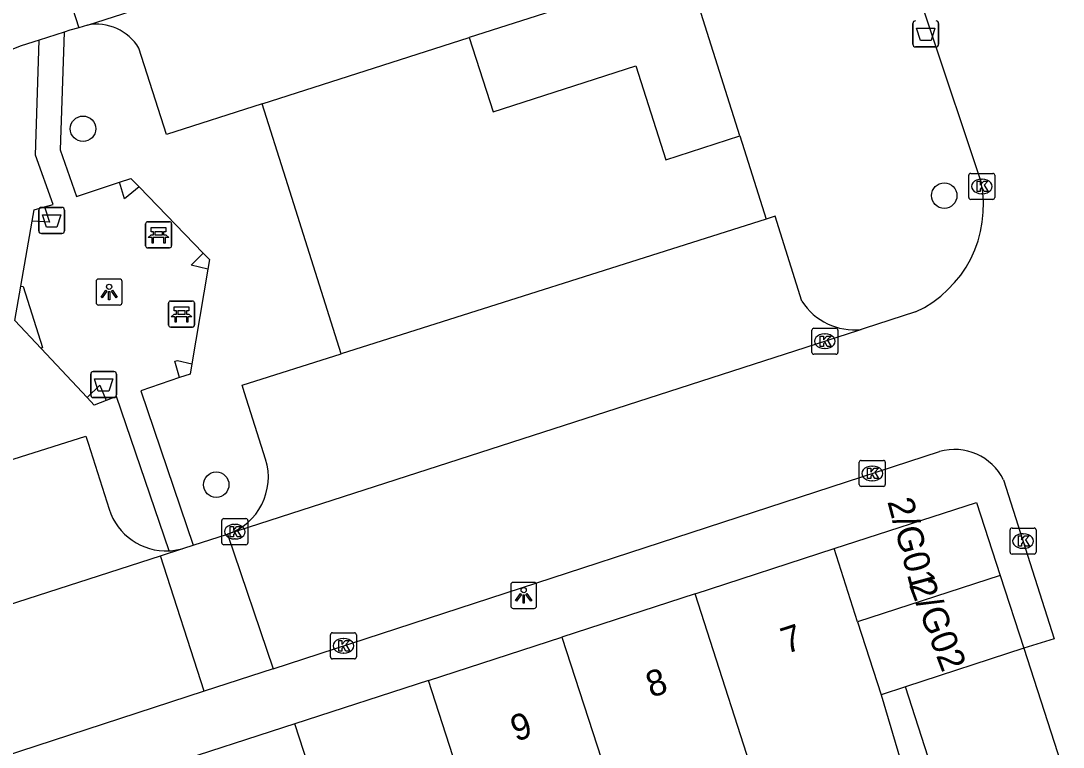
# Model space of a CAD drawing. Extents: x 159377 to 159983, y 382996 to 383595.
# Drawn here: x 159543.65 to 159583.72, y 383099.82 to 383127.71 of the extents above; entities that cross this region are included whole.
import ezdxf

# ---------------------------------------------------------------- set-up
doc = ezdxf.new("R2010")
doc.units = 0
for name, color, linetype in [('IMGEO_Afvalbak', 7, 'Continuous'), ('IMGEO_Bank', 7, 'Continuous'), ('IMGEO_Boom', 7, 'Continuous'), ('IMGEO_Groenvoorziening', 7, 'Continuous'), ('IMGEO_Kolk', 7, 'Continuous'), ('IMGEO_Lichtpunt', 7, 'Continuous'), ('IMGEO_Pand', 7, 'Continuous'), ('IMGEO_Pand_nummerreeks', 7, 'Continuous'), ('IMGEO_Parkeervlak_open', 7, 'Continuous'), ('IMGEO_Rijbaan_lokaal_open', 7, 'Continuous'), ('IMGEO_Voetpad_halfverhard', 7, 'Continuous'), ('IMGEO_Voetpad_open', 7, 'Continuous')]:
    doc.layers.add(name, color=color, linetype=linetype)

msp = doc.modelspace()

# ---------------------------------------------------------------- linework, layer by layer
at = {"layer": 'IMGEO_Afvalbak'}
for p, q in [((159577.943, 383126.815), (159577.943, 383127.615)), ((159577.943, 383127.615), (159577.943, 383126.815)), ((159578.933, 383127.615), (159578.933, 383126.815)), ((159578.933, 383126.815), (159578.933, 383127.615)), ((159578.833, 383126.715), (159578.043, 383126.715)), ((159578.043, 383126.715), (159578.833, 383126.715)), ((159544.338, 383119.648), (159544.338, 383120.448)), ((159544.338, 383120.448), (159544.338, 383119.648)), ((159544.438, 383120.548), (159545.228, 383120.548)), ((159545.228, 383120.548), (159544.438, 383120.548)), ((159545.328, 383120.448), (159545.328, 383119.648)), ((159545.328, 383119.648), (159545.328, 383120.448)), ((159545.228, 383119.548), (159544.438, 383119.548)), ((159544.438, 383119.548), (159545.228, 383119.548)), ((159546.336, 383113.344), (159546.336, 383114.144)), ((159546.336, 383114.144), (159546.336, 383113.344)), ((159546.436, 383114.244), (159547.226, 383114.244)), ((159547.226, 383114.244), (159546.436, 383114.244)), ((159547.326, 383114.144), (159547.326, 383113.344)), ((159547.326, 383113.344), (159547.326, 383114.144)), ((159547.226, 383113.244), (159546.436, 383113.244)), ((159546.436, 383113.244), (159547.226, 383113.244))]:
    msp.add_line(p, q, dxfattribs=at)
for points in [[(159578.086, 383127.429), (159578.79, 383127.429), (159578.641, 383126.959), (159578.235, 383126.959), (159578.086, 383127.429)], [(159544.481, 383120.262), (159545.185, 383120.262), (159545.036, 383119.792), (159544.63, 383119.792), (159544.481, 383120.262)], [(159546.479, 383113.958), (159547.183, 383113.958), (159547.034, 383113.488), (159546.628, 383113.488), (159546.479, 383113.958)]]:
    msp.add_lwpolyline(points, dxfattribs=at)
for centre, start, end in [((159578.043, 383127.615), 90, 180), ((159578.043, 383127.615), 90, 180), ((159578.833, 383127.615), 0, 90), ((159578.833, 383127.615), 360, 90), ((159578.043, 383126.815), 180, 270), ((159578.043, 383126.815), 180, 270), ((159578.833, 383126.815), 270, 0), ((159578.833, 383126.815), 270, 0), ((159544.438, 383120.448), 90, 180), ((159544.438, 383120.448), 90, 180), ((159545.228, 383120.448), 0, 90), ((159545.228, 383120.448), 360, 90), ((159544.438, 383119.648), 180, 270), ((159544.438, 383119.648), 180, 270), ((159545.228, 383119.648), 270, 0), ((159545.228, 383119.648), 270, 0), ((159546.436, 383114.144), 90, 180), ((159546.436, 383114.144), 90, 180), ((159547.226, 383114.144), 0, 90), ((159547.226, 383114.144), 360, 90), ((159546.436, 383113.344), 180, 270), ((159546.436, 383113.344), 180, 270), ((159547.226, 383113.344), 270, 0), ((159547.226, 383113.344), 270, 0)]:
    msp.add_arc(centre, 0.1, start, end, dxfattribs=at)
at = {"layer": 'IMGEO_Bank'}
for p, q in [((159548.445, 383119.071), (159548.445, 383119.912)), ((159548.445, 383119.912), (159548.445, 383119.071)), ((159548.52, 383119.996), (159549.361, 383119.996)), ((159549.361, 383119.996), (159548.52, 383119.996)), ((159549.445, 383119.921), (159549.445, 383119.08)), ((159549.445, 383119.08), (159549.445, 383119.921)), ((159549.142, 383119.394), (159548.749, 383119.394)), ((159548.754, 383119.502), (159548.754, 383119.608)), ((159548.798, 383119.608), (159548.798, 383119.502)), ((159549.086, 383119.614), (159548.804, 383119.614)), ((159548.804, 383119.496), (159549.086, 383119.496)), ((159549.092, 383119.502), (159549.092, 383119.608)), ((159549.136, 383119.608), (159549.136, 383119.502)), ((159549.37, 383118.996), (159548.529, 383118.996)), ((159548.529, 383118.996), (159549.37, 383118.996)), ((159549.326, 383116.028), (159549.326, 383116.869)), ((159549.326, 383116.869), (159549.326, 383116.028)), ((159549.401, 383116.953), (159550.242, 383116.953)), ((159550.242, 383116.953), (159549.401, 383116.953)), ((159550.326, 383116.878), (159550.326, 383116.037)), ((159550.326, 383116.037), (159550.326, 383116.878)), ((159549.635, 383116.459), (159549.635, 383116.565)), ((159549.679, 383116.565), (159549.679, 383116.459)), ((159549.967, 383116.571), (159549.685, 383116.571)), ((159549.685, 383116.453), (159549.967, 383116.453)), ((159549.973, 383116.459), (159549.973, 383116.565)), ((159550.017, 383116.565), (159550.017, 383116.459)), ((159550.023, 383116.351), (159549.63, 383116.351)), ((159550.251, 383115.953), (159549.41, 383115.953)), ((159549.41, 383115.953), (159550.251, 383115.953))]:
    msp.add_line(p, q, dxfattribs=at)
for points in [[(159548.748, 383119.614), (159548.662, 383119.614), (159548.662, 383119.775), (159549.225, 383119.775), (159549.225, 383119.614), (159549.142, 383119.614)], [(159548.692, 383119.394), (159548.55, 383119.394), (159548.662, 383119.496), (159548.748, 383119.496)], [(159548.742, 383119.387), (159548.742, 383119.18), (159548.699, 383119.18), (159548.699, 383119.387)], [(159549.142, 383119.496), (159549.225, 383119.496), (159549.337, 383119.394), (159549.198, 383119.394)], [(159549.192, 383119.387), (159549.192, 383119.18), (159549.148, 383119.18), (159549.148, 383119.387)], [(159549.573, 383116.351), (159549.431, 383116.351), (159549.543, 383116.453), (159549.629, 383116.453)], [(159549.629, 383116.571), (159549.543, 383116.571), (159549.543, 383116.732), (159550.106, 383116.732), (159550.106, 383116.571), (159550.023, 383116.571)], [(159550.023, 383116.453), (159550.106, 383116.453), (159550.218, 383116.351), (159550.079, 383116.351)], [(159549.623, 383116.344), (159549.623, 383116.137), (159549.58, 383116.137), (159549.58, 383116.344)], [(159550.073, 383116.344), (159550.073, 383116.137), (159550.029, 383116.137), (159550.029, 383116.344)]]:
    msp.add_lwpolyline(points, dxfattribs=at)
for centre, radius, start, end in [((159548.523, 383119.918), 0.0779, 92.4484, 184.2845), ((159548.523, 383119.918), 0.0779, 92.4484, 184.2845), ((159549.367, 383119.918), 0.0779, 2.4484, 94.2845), ((159549.367, 383119.918), 0.0779, 2.4484, 94.2845), ((159548.692, 383119.387), 0.00671, 2.8957, 87.1043), ((159548.749, 383119.387), 0.00671, 92.8957, 177.1043), ((159548.747, 383119.607), 0.00671, 2.8957, 87.1043), ((159548.747, 383119.503), 0.00671, 272.8957, 357.1043), ((159548.804, 383119.607), 0.00671, 92.8957, 177.1043), ((159548.804, 383119.503), 0.00671, 182.8957, 267.1043), ((159549.086, 383119.607), 0.00671, 2.8957, 87.1043), ((159549.086, 383119.503), 0.00671, 272.8957, 357.1043), ((159549.143, 383119.607), 0.00671, 92.8957, 177.1043), ((159549.143, 383119.503), 0.00671, 182.8957, 267.1043), ((159549.141, 383119.387), 0.00671, 2.8957, 87.1043), ((159549.198, 383119.387), 0.00671, 92.8957, 177.1043), ((159548.523, 383119.074), 0.0779, 182.4484, 274.2845), ((159548.523, 383119.074), 0.0779, 182.4484, 274.2845), ((159549.367, 383119.074), 0.0779, 272.4484, 4.2845), ((159549.367, 383119.074), 0.0779, 272.4484, 4.2845), ((159549.404, 383116.875), 0.0779, 92.4484, 184.2845), ((159549.404, 383116.875), 0.0779, 92.4484, 184.2845), ((159550.248, 383116.875), 0.0779, 2.4484, 94.2845), ((159550.248, 383116.875), 0.0779, 2.4484, 94.2845), ((159549.628, 383116.564), 0.00671, 2.8957, 87.1043), ((159549.628, 383116.46), 0.00671, 272.8957, 357.1043), ((159549.685, 383116.564), 0.00671, 92.8957, 177.1043), ((159549.685, 383116.46), 0.00671, 182.8957, 267.1043), ((159549.967, 383116.564), 0.00671, 2.8957, 87.1043), ((159549.967, 383116.46), 0.00671, 272.8957, 357.1043), ((159550.024, 383116.564), 0.00671, 92.8957, 177.1043), ((159550.024, 383116.46), 0.00671, 182.8957, 267.1043), ((159549.404, 383116.031), 0.0779, 182.4484, 274.2845), ((159549.404, 383116.031), 0.0779, 182.4484, 274.2845), ((159549.573, 383116.344), 0.00671, 2.8957, 87.1043), ((159549.63, 383116.344), 0.00671, 92.8957, 177.1043), ((159550.022, 383116.344), 0.00671, 2.8957, 87.1043), ((159550.079, 383116.344), 0.00671, 92.8957, 177.1043), ((159550.248, 383116.031), 0.0779, 272.4484, 4.2845), ((159550.248, 383116.031), 0.0779, 272.4484, 4.2845)]:
    msp.add_arc(centre, radius, start, end, dxfattribs=at)
at = {"layer": 'IMGEO_Boom'}
for centre in [(159546.04, 383123.57), (159579.15, 383121.002), (159551.161, 383109.897)]:
    msp.add_circle(centre, 0.489, dxfattribs=at)
at = {"layer": 'IMGEO_Groenvoorziening'}
for points in [[(159571.294, 383123.299), (159569.251, 383129.752)], [(159560.89, 383127.076), (159561.803, 383124.221), (159567.297, 383125.984), (159568.44, 383122.376), (159571.294, 383123.299)], [(159555.969, 383114.93), (159553.836, 383121.665), (159552.93, 383124.528)], [(159571.294, 383123.299), (159571.459, 383122.778), (159572.307, 383120.099)], [(159547.442, 383121.513), (159547.884, 383121.66), (159548.198, 383121.336)], [(159544.083, 383120.022), (159544.158, 383120.452), (159544.563, 383120.57)], [(159550.658, 383118.797), (159550.906, 383118.542), (159550.844, 383118.175)], [(159544.43, 383115.124), (159543.419, 383116.198), (159543.65, 383117.526)], [(159550.226, 383114.542), (159550.158, 383114.146), (159549.753, 383114.009)], [(159546.924, 383113.129), (159546.472, 383112.957), (159546.197, 383113.249)]]:
    msp.add_lwpolyline(points, dxfattribs=at)
at = {"layer": 'IMGEO_Kolk'}
for p, q in [((159580.093, 383120.93), (159580.093, 383121.782)), ((159580.168, 383121.856), (159581.02, 383121.856)), ((159581.094, 383121.782), (159581.094, 383120.93)), ((159580.581, 383121.636), (159580.606, 383121.636)), ((159581.02, 383120.856), (159580.168, 383120.856)), ((159580.604, 383121.076), (159580.579, 383121.076)), ((159574.059, 383114.981), (159574.059, 383115.833)), ((159574.134, 383115.907), (159574.986, 383115.907)), ((159574.547, 383115.687), (159574.572, 383115.687)), ((159575.06, 383115.833), (159575.06, 383114.981)), ((159574.986, 383114.907), (159574.134, 383114.907)), ((159574.57, 383115.127), (159574.545, 383115.127)), ((159575.958, 383110.83), (159576.81, 383110.83)), ((159575.883, 383109.904), (159575.883, 383110.756)), ((159576.371, 383110.61), (159576.396, 383110.61)), ((159576.884, 383110.756), (159576.884, 383109.904)), ((159576.394, 383110.05), (159576.369, 383110.05)), ((159576.81, 383109.83), (159575.958, 383109.83)), ((159551.376, 383107.666), (159551.376, 383108.518)), ((159551.451, 383108.592), (159552.303, 383108.592)), ((159552.377, 383108.518), (159552.377, 383107.666)), ((159551.864, 383108.372), (159551.889, 383108.372)), ((159581.68, 383107.307), (159581.68, 383108.159)), ((159581.755, 383108.233), (159582.607, 383108.233)), ((159582.168, 383108.013), (159582.193, 383108.013)), ((159582.681, 383108.159), (159582.681, 383107.307)), ((159551.887, 383107.812), (159551.862, 383107.812)), ((159552.303, 383107.592), (159551.451, 383107.592)), ((159582.607, 383107.233), (159581.755, 383107.233)), ((159582.191, 383107.453), (159582.166, 383107.453)), ((159555.552, 383103.28), (159555.552, 383104.132)), ((159555.627, 383104.206), (159556.479, 383104.206)), ((159556.553, 383104.132), (159556.553, 383103.28)), ((159556.04, 383103.986), (159556.065, 383103.986)), ((159556.479, 383103.206), (159555.627, 383103.206)), ((159556.063, 383103.426), (159556.038, 383103.426))]:
    msp.add_line(p, q, dxfattribs=at)
for points in [[(159580.093, 383120.93), (159580.093, 383121.782)], [(159580.168, 383121.856), (159581.02, 383121.856)], [(159581.094, 383121.782), (159581.094, 383120.93)], [(159580.414, 383121.556), (159580.537, 383121.556), (159580.537, 383121.405), (159580.667, 383121.556), (159580.831, 383121.556), (159580.685, 383121.405), (159580.838, 383121.156), (159580.686, 383121.156), (159580.601, 383121.32), (159580.537, 383121.253), (159580.537, 383121.156), (159580.414, 383121.156), (159580.414, 383121.556)], [(159581.02, 383120.856), (159580.168, 383120.856)], [(159574.059, 383114.981), (159574.059, 383115.833)], [(159574.134, 383115.907), (159574.986, 383115.907)], [(159575.06, 383115.833), (159575.06, 383114.981)], [(159574.38, 383115.607), (159574.503, 383115.607), (159574.503, 383115.456), (159574.633, 383115.607), (159574.797, 383115.607), (159574.651, 383115.456), (159574.804, 383115.207), (159574.652, 383115.207), (159574.567, 383115.371), (159574.503, 383115.304), (159574.503, 383115.207), (159574.38, 383115.207), (159574.38, 383115.607)], [(159574.986, 383114.907), (159574.134, 383114.907)], [(159575.958, 383110.83), (159576.81, 383110.83)], [(159575.883, 383109.904), (159575.883, 383110.756)], [(159576.204, 383110.53), (159576.327, 383110.53), (159576.327, 383110.379), (159576.457, 383110.53), (159576.621, 383110.53), (159576.475, 383110.379), (159576.628, 383110.13), (159576.476, 383110.13), (159576.391, 383110.294), (159576.327, 383110.227), (159576.327, 383110.13), (159576.204, 383110.13), (159576.204, 383110.53)], [(159576.884, 383110.756), (159576.884, 383109.904)], [(159576.81, 383109.83), (159575.958, 383109.83)], [(159551.376, 383107.666), (159551.376, 383108.518)], [(159551.451, 383108.592), (159552.303, 383108.592)], [(159552.377, 383108.518), (159552.377, 383107.666)], [(159551.697, 383108.292), (159551.82, 383108.292), (159551.82, 383108.141), (159551.95, 383108.292), (159552.114, 383108.292), (159551.968, 383108.141), (159552.121, 383107.892), (159551.969, 383107.892), (159551.884, 383108.056), (159551.82, 383107.989), (159551.82, 383107.892), (159551.697, 383107.892), (159551.697, 383108.292)], [(159581.68, 383107.307), (159581.68, 383108.159)], [(159581.755, 383108.233), (159582.607, 383108.233)], [(159582.681, 383108.159), (159582.681, 383107.307)], [(159582.001, 383107.933), (159582.124, 383107.933), (159582.124, 383107.782), (159582.254, 383107.933), (159582.418, 383107.933), (159582.272, 383107.782), (159582.425, 383107.533), (159582.273, 383107.533), (159582.188, 383107.697), (159582.124, 383107.63), (159582.124, 383107.533), (159582.001, 383107.533), (159582.001, 383107.933)], [(159552.303, 383107.592), (159551.451, 383107.592)], [(159582.607, 383107.233), (159581.755, 383107.233)], [(159555.552, 383103.28), (159555.552, 383104.132)], [(159555.627, 383104.206), (159556.479, 383104.206)], [(159556.553, 383104.132), (159556.553, 383103.28)], [(159555.873, 383103.906), (159555.996, 383103.906), (159555.996, 383103.755), (159556.126, 383103.906), (159556.29, 383103.906), (159556.144, 383103.755), (159556.297, 383103.506), (159556.145, 383103.506), (159556.06, 383103.67), (159555.996, 383103.603), (159555.996, 383103.506), (159555.873, 383103.506), (159555.873, 383103.906)], [(159556.479, 383103.206), (159555.627, 383103.206)]]:
    msp.add_lwpolyline(points, dxfattribs=at)
for centre, start, end in [((159580.17, 383121.78), 91.552, 178.448), ((159580.17, 383121.78), 91.552, 178.448), ((159581.018, 383121.78), 1.552, 88.448), ((159581.018, 383121.78), 1.552, 88.448), ((159580.17, 383120.932), 181.552, 268.448), ((159580.17, 383120.932), 181.552, 268.448), ((159581.018, 383120.932), 271.552, 358.448), ((159581.018, 383120.932), 271.552, 358.448), ((159574.136, 383115.831), 91.552, 178.448), ((159574.136, 383115.831), 91.552, 178.448), ((159574.984, 383115.831), 1.552, 88.448), ((159574.984, 383115.831), 1.552, 88.448), ((159574.136, 383114.983), 181.552, 268.448), ((159574.136, 383114.983), 181.552, 268.448), ((159574.984, 383114.983), 271.552, 358.448), ((159574.984, 383114.983), 271.552, 358.448), ((159575.96, 383110.754), 91.552, 178.448), ((159575.96, 383110.754), 91.552, 178.448), ((159576.808, 383110.754), 1.552, 88.448), ((159576.808, 383110.754), 1.552, 88.448), ((159575.96, 383109.906), 181.552, 268.448), ((159575.96, 383109.906), 181.552, 268.448), ((159576.808, 383109.906), 271.552, 358.448), ((159576.808, 383109.906), 271.552, 358.448), ((159551.453, 383108.516), 91.552, 178.448), ((159551.453, 383108.516), 91.552, 178.448), ((159552.301, 383108.516), 1.552, 88.448), ((159552.301, 383108.516), 1.552, 88.448), ((159581.757, 383108.157), 91.552, 178.448), ((159581.757, 383108.157), 91.552, 178.448), ((159582.605, 383108.157), 1.552, 88.448), ((159582.605, 383108.157), 1.552, 88.448), ((159551.453, 383107.668), 181.552, 268.448), ((159551.453, 383107.668), 181.552, 268.448), ((159552.301, 383107.668), 271.552, 358.448), ((159552.301, 383107.668), 271.552, 358.448), ((159581.757, 383107.309), 181.552, 268.448), ((159581.757, 383107.309), 181.552, 268.448), ((159582.605, 383107.309), 271.552, 358.448), ((159582.605, 383107.309), 271.552, 358.448), ((159555.629, 383104.13), 91.552, 178.448), ((159555.629, 383104.13), 91.552, 178.448), ((159556.477, 383104.13), 1.552, 88.448), ((159556.477, 383104.13), 1.552, 88.448), ((159555.629, 383103.282), 181.552, 268.448), ((159555.629, 383103.282), 181.552, 268.448), ((159556.477, 383103.282), 271.552, 358.448), ((159556.477, 383103.282), 271.552, 358.448)]:
    msp.add_arc(centre, 0.0765, start, end, dxfattribs=at)
for centre, major_axis, ratio, start_param, end_param in [((159580.58, 383121.356), (-0.387, 0.002), 0.722429, 4.712389, 7.853982), ((159580.605, 383121.356), (-0.39, 0.002), 0.717154, 1.570796, 4.712389), ((159574.546, 383115.407), (-0.387, 0.002), 0.722429, 4.712389, 7.853982), ((159574.571, 383115.407), (-0.39, 0.002), 0.717154, 1.570796, 4.712389), ((159576.37, 383110.33), (-0.387, 0.002), 0.722429, 4.712389, 7.853982), ((159576.395, 383110.33), (-0.39, 0.002), 0.717154, 1.570796, 4.712389), ((159551.863, 383108.092), (-0.387, 0.002), 0.722429, 4.712389, 7.853982), ((159551.888, 383108.092), (-0.39, 0.002), 0.717154, 1.570796, 4.712389), ((159582.167, 383107.733), (-0.387, 0.002), 0.722429, 4.712389, 7.853982), ((159582.192, 383107.733), (-0.39, 0.002), 0.717154, 1.570796, 4.712389), ((159556.039, 383103.706), (-0.387, 0.002), 0.722429, 4.712389, 7.853982), ((159556.064, 383103.706), (-0.39, 0.002), 0.717154, 1.570796, 4.712389)]:
    msp.add_ellipse(centre, major_axis=major_axis, ratio=ratio, start_param=start_param, end_param=end_param, dxfattribs=at)
at = {"layer": 'IMGEO_Lichtpunt'}
for p, q in [((159546.545, 383117.701), (159546.545, 383116.894)), ((159546.545, 383117.701), (159546.545, 383116.894)), ((159547.447, 383117.796), (159546.639, 383117.796)), ((159547.447, 383117.796), (159546.639, 383117.796)), ((159547.541, 383116.894), (159547.541, 383117.701)), ((159547.541, 383116.894), (159547.541, 383117.701)), ((159546.639, 383116.8), (159547.447, 383116.8)), ((159546.639, 383116.8), (159547.447, 383116.8)), ((159562.483, 383106.048), (159562.483, 383105.241)), ((159562.483, 383106.048), (159562.483, 383105.241)), ((159563.385, 383106.143), (159562.577, 383106.143)), ((159563.385, 383106.143), (159562.577, 383106.143)), ((159563.479, 383105.241), (159563.479, 383106.048)), ((159563.479, 383105.241), (159563.479, 383106.048)), ((159562.577, 383105.147), (159563.385, 383105.147)), ((159562.577, 383105.147), (159563.385, 383105.147))]:
    msp.add_line(p, q, dxfattribs=at)
for points in [[(159546.919, 383117.365), (159546.958, 383117.337), (159546.77, 383117.075), (159546.732, 383117.102), (159546.919, 383117.365)], [(159547.021, 383117.317), (159547.068, 383117.317), (159547.068, 383116.995), (159547.021, 383116.995), (159547.021, 383117.317)], [(159547.131, 383117.337), (159547.169, 383117.364), (159547.356, 383117.102), (159547.317, 383117.074), (159547.131, 383117.337)], [(159562.857, 383105.712), (159562.896, 383105.684), (159562.708, 383105.422), (159562.67, 383105.449), (159562.857, 383105.712)], [(159562.959, 383105.664), (159563.006, 383105.664), (159563.006, 383105.342), (159562.959, 383105.342), (159562.959, 383105.664)], [(159563.069, 383105.684), (159563.107, 383105.711), (159563.294, 383105.449), (159563.255, 383105.421), (159563.069, 383105.684)]]:
    msp.add_lwpolyline(points, dxfattribs=at)
for centre in [(159547.044, 383117.499), (159562.982, 383105.846)]:
    msp.add_circle(centre, 0.0994, dxfattribs=at)
for centre, start, end in [((159546.639, 383117.701), 90, 180), ((159546.639, 383117.701), 90, 180), ((159547.447, 383117.701), 0, 90), ((159547.447, 383117.701), 0, 90), ((159546.639, 383116.894), 180, 270), ((159546.639, 383116.894), 180, 270), ((159547.447, 383116.894), 270, 0), ((159547.447, 383116.894), 270, 360), ((159562.577, 383106.048), 90, 180), ((159562.577, 383106.048), 90, 180), ((159563.385, 383106.048), 0, 90), ((159563.385, 383106.048), 0, 90), ((159562.577, 383105.241), 180, 270), ((159562.577, 383105.241), 180, 270), ((159563.385, 383105.241), 270, 0), ((159563.385, 383105.241), 270, 360)]:
    msp.add_arc(centre, 0.0946, start, end, dxfattribs=at)
at = {"layer": 'IMGEO_Pand'}
for points in [[(159574.918, 383107.441), (159580.39, 383109.217), (159581.3, 383106.414)], [(159569.577, 383105.707), (159574.918, 383107.441)], [(159575.821, 383104.635), (159574.918, 383107.441)], [(159581.3, 383106.414), (159575.821, 383104.635)], [(159581.3, 383106.414), (159582.21, 383103.611)], [(159569.577, 383105.707), (159564.446, 383104.041)], [(159572.256, 383097.384), (159569.577, 383105.707)], [(159575.821, 383104.635), (159576.724, 383101.831)], [(159559.316, 383102.376), (159564.446, 383104.041)], [(159564.446, 383104.041), (159567.152, 383095.728)], [(159582.21, 383103.611), (159577.654, 383102.133)], [(159559.316, 383102.376), (159554.184, 383100.71)], [(159562.01, 383094.058), (159559.316, 383102.376)], [(159577.654, 383102.133), (159576.724, 383101.831)], [(159576.724, 383101.831), (159577.533, 383099.097)], [(159554.184, 383100.71), (159549.045, 383099.042)], [(159556.888, 383092.396), (159554.184, 383100.71)]]:
    msp.add_lwpolyline(points, dxfattribs=at)
at = {"layer": 'IMGEO_Parkeervlak_open'}
for points in [[(159569.251, 383129.752), (159560.89, 383127.076)], [(159552.93, 383124.528), (159560.89, 383127.076)], [(159552.93, 383124.528), (159549.248, 383123.349), (159548.186, 383126.668)], [(159572.307, 383120.099), (159555.969, 383114.93)], [(159573.679, 383116.948), (159572.649, 383120.207), (159572.307, 383120.099)], [(159553.057, 383110.875), (159552.25, 383113.426), (159552.156, 383113.724), (159555.969, 383114.93)], [(159542.373, 383110.568), (159546.154, 383111.766), (159546.242, 383111.488), (159547.042, 383108.961)]]:
    msp.add_lwpolyline(points, dxfattribs=at)
for centre, radius, start, end in [((159546.565, 383125.692), 1.893, 31.055, 100.7673), ((159575.69, 383118.23), 2.385, 212.5102, 276.489), ((159550.862, 383110.182), 2.302, 288.4865, 17.526), ((159549.233, 383109.652), 2.297, 197.4994, 273.0305)]:
    msp.add_arc(centre, radius, start, end, dxfattribs=at)
at = {"layer": 'IMGEO_Rijbaan_lokaal_open'}
for points in [[(159546.211, 383127.551), (159568.704, 383134.767)], [(159576.594, 383133.402), (159580.568, 383121.503)], [(159544.136, 383132.87), (159545.88, 383127.445)], [(159545.314, 383127.28), (159544.352, 383126.971)], [(159545.88, 383127.445), (159545.538, 383127.352), (159545.314, 383127.28)], [(159546.211, 383127.551), (159545.88, 383127.445)], [(159544.352, 383126.971), (159543.66, 383126.749), (159543.244, 383126.59)], [(159578.043, 383116.532), (159576.075, 383115.897), (159575.96, 383115.86)], [(159575.96, 383115.86), (159575.853, 383115.826), (159551.592, 383107.999)], [(159553.35, 383102.825), (159578.967, 383111.171)], [(159581.43, 383110.08), (159583.382, 383103.973), (159582.21, 383103.611)], [(159550.271, 383107.573), (159551.592, 383107.999)], [(159551.592, 383107.999), (159553.35, 383102.825)], [(159549.018, 383107.169), (159549.915, 383107.458)], [(159549.915, 383107.458), (159550.271, 383107.573)], [(159530.567, 383101.218), (159549.018, 383107.169)], [(159550.697, 383101.96), (159549.018, 383107.169)], [(159582.21, 383103.611), (159588.82, 383083.137)], [(159553.35, 383102.825), (159550.697, 383101.96)], [(159550.697, 383101.96), (159526.127, 383093.955), (159526.812, 383091.837)]]:
    msp.add_lwpolyline(points, dxfattribs=at)
for centre, radius, start, end in [((159576.16, 383120.615), 4.497, 294.7577, 11.386), ((159579.545, 383109.15), 2.102, 26.2595, 105.9581)]:
    msp.add_arc(centre, radius, start, end, dxfattribs=at)
at = {"layer": 'IMGEO_Voetpad_halfverhard'}
for points in [[(159545.314, 383127.28), (159545.161, 383122.758), (159545.794, 383120.965), (159547.442, 383121.513)], [(159544.563, 383120.57), (159544.892, 383120.666), (159544.217, 383122.557), (159544.352, 383126.971)], [(159548.198, 383121.336), (159547.633, 383120.882), (159547.442, 383121.513)], [(159548.198, 383121.336), (159550.658, 383118.797)], [(159544.563, 383120.57), (159544.745, 383119.98), (159544.083, 383120.022)], [(159543.65, 383117.526), (159544.083, 383120.022)], [(159550.844, 383118.175), (159550.196, 383118.336), (159550.658, 383118.797)], [(159550.844, 383118.175), (159550.226, 383114.542)], [(159543.65, 383117.526), (159543.736, 383117.513), (159544.479, 383115.166), (159544.43, 383115.124)], [(159546.197, 383113.249), (159544.43, 383115.124)], [(159549.753, 383114.009), (159549.569, 383114.637), (159549.669, 383114.673), (159550.226, 383114.542)], [(159546.197, 383113.249), (159546.69, 383113.715), (159546.924, 383113.129)], [(159549.753, 383114.009), (159548.266, 383113.506), (159550.271, 383107.573)], [(159549.354, 383107.358), (159547.332, 383113.284), (159546.924, 383113.129)]]:
    msp.add_lwpolyline(points, dxfattribs=at)
msp.add_arc((159549.248, 383109.578), 2.223, 272.7431, 287.4709, dxfattribs=at)
at = {"layer": 'IMGEO_Voetpad_open'}
msp.add_lwpolyline([(159588.82, 383083.137), (159584.26, 383081.67), (159577.654, 383102.133)], dxfattribs=at)

# ---------------------------------------------------------------- texts
at = {"layer": 'IMGEO_Pand_nummerreeks'}
for s, rotation, p in [('2/G01', 285.0685, (159576.957, 383109.253)), ('2/G02', 291.0375, (159577.784, 383106.046)), ('7', 17.985, (159573.07, 383103.392)), ('8', 17.985, (159567.878, 383101.706)), ('9', 17.985, (159562.678, 383100.018))]:
    msp.add_text(s, height=1, rotation=rotation, dxfattribs=at).set_placement(p)

doc.saveas('drawing.dxf')
